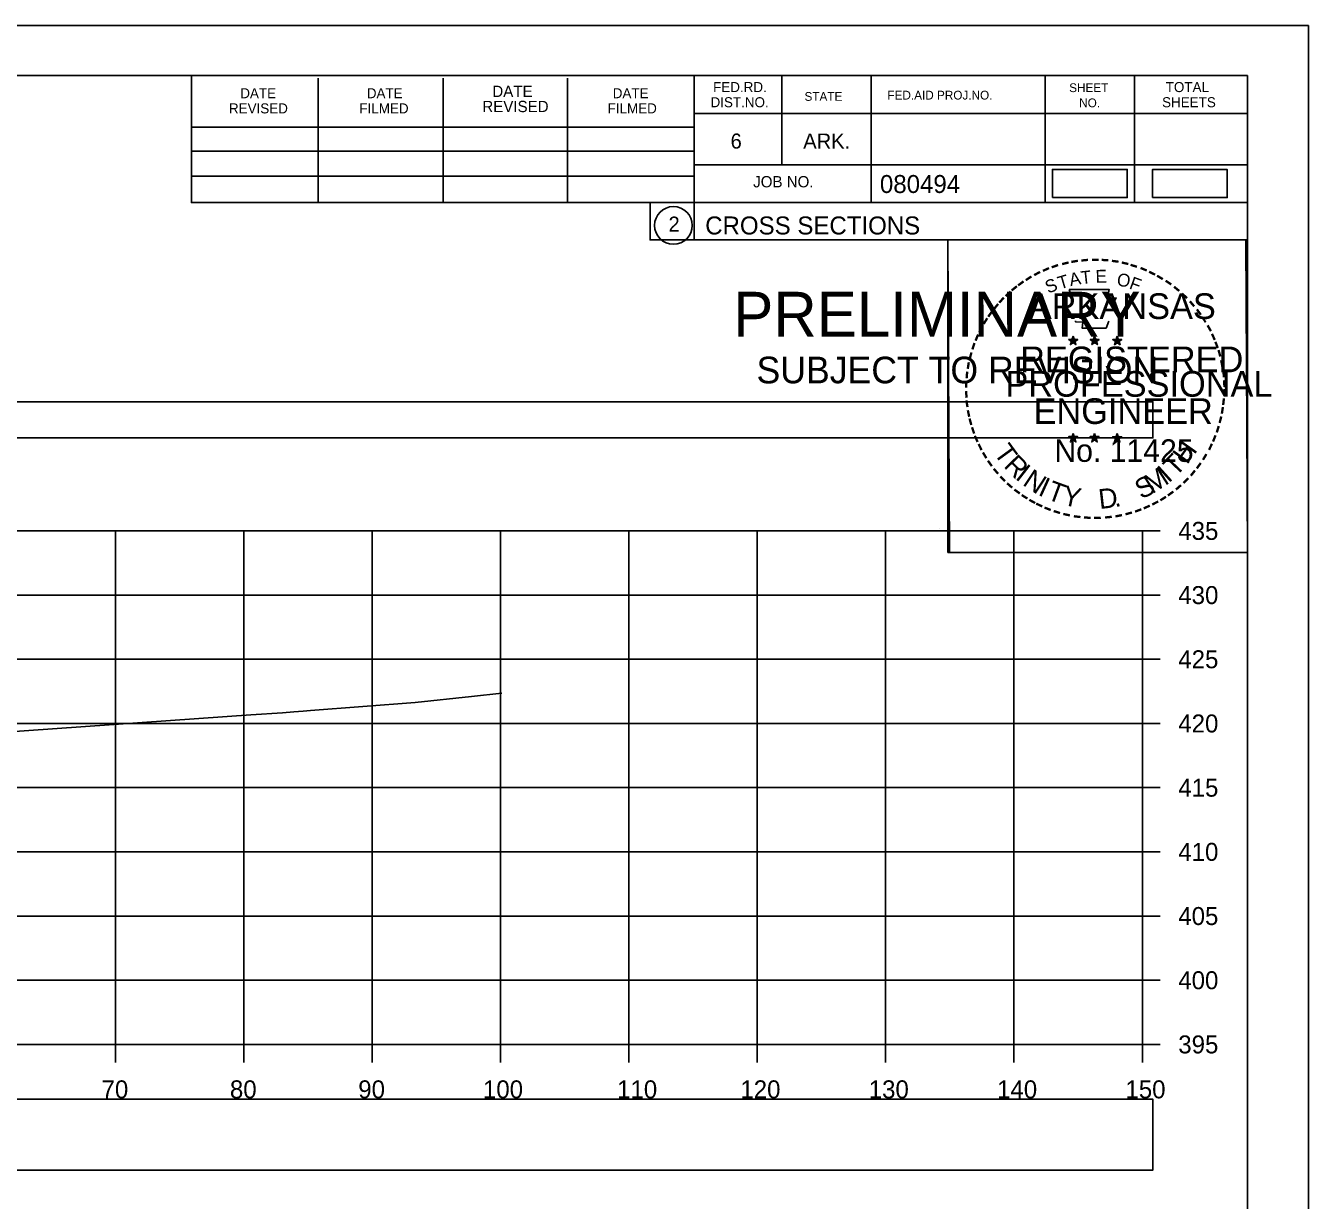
# Model space of a CAD drawing. Extents: x 1376273 to 1384221, y 378927 to 384592.
# Drawn here: x 1379454.1 to 1379554.1, y 380020.3 to 380111.8 of the extents above; entities that cross this region are included whole.
import ezdxf

# ---------------------------------------------------------------- set-up
doc = ezdxf.new("R2010")
doc.units = 0
for name, color, linetype in [('R_Axis', 7, 'Continuous'), ('R_Axis Annot', 7, 'Continuous'), ('R_Border', 7, 'Continuous'), ('R_Border PE', 7, 'Continuous'), ('R_Border Prem', 7, 'Continuous'), ('R_Drive', 7, 'Continuous'), ('R_Exist Surface', 7, 'Continuous'), ('R_Grid', 7, 'Continuous'), ('R_No Plot', 7, 'Continuous')]:
    doc.layers.add(name, color=color, linetype=linetype)

msp = doc.modelspace()

# ---------------------------------------------------------------- linework, layer by layer
at = {"layer": 'R_Axis'}
for p, q in [((1379541.147, 380032.48), (1379541.147, 380072.48)), ((1379542.547, 380072.48), (1379541.147, 380072.48)), ((1379542.547, 380067.48), (1379541.147, 380067.48)), ((1379542.547, 380062.48), (1379541.147, 380062.48)), ((1379542.547, 380057.48), (1379541.147, 380057.48)), ((1379542.547, 380052.48), (1379541.147, 380052.48)), ((1379542.547, 380047.48), (1379541.147, 380047.48)), ((1379542.547, 380042.48), (1379541.147, 380042.48)), ((1379542.547, 380037.48), (1379541.147, 380037.48)), ((1379241.147, 380032.48), (1379541.147, 380032.48)), ((1379461.147, 380031.08), (1379461.147, 380032.48)), ((1379471.147, 380031.08), (1379471.147, 380032.48)), ((1379481.147, 380031.08), (1379481.147, 380032.48)), ((1379491.147, 380031.08), (1379491.147, 380032.48)), ((1379501.147, 380031.08), (1379501.147, 380032.48)), ((1379511.147, 380031.08), (1379511.147, 380032.48)), ((1379521.147, 380031.08), (1379521.147, 380032.48)), ((1379531.147, 380031.08), (1379531.147, 380032.48)), ((1379541.147, 380031.08), (1379541.147, 380032.48)), ((1379542.547, 380032.48), (1379541.147, 380032.48))]:
    msp.add_line(p, q, dxfattribs=at)
at = {"layer": 'R_Axis Annot'}
for points in [[(1379240.169, 380079.723), (1379541.971, 380079.723), (1379541.971, 380082.54), (1379240.169, 380082.54)], [(1379240.169, 380022.687), (1379541.971, 380022.687), (1379541.971, 380028.21), (1379240.169, 380028.21)]]:
    msp.add_lwpolyline(points, close=True, dxfattribs=at)
at = {"layer": 'R_Border'}
for p, q in [((1379233.147, 380107.94), (1379549.327, 380107.94)), ((1379467.067, 380098.06), (1379467.067, 380107.94)), ((1379476.927, 380098.06), (1379476.927, 380107.74)), ((1379486.687, 380098.06), (1379486.687, 380107.74)), ((1379496.367, 380098.06), (1379496.367, 380107.74)), ((1379506.227, 380107.94), (1379506.227, 380095.14)), ((1379513.067, 380107.94), (1379513.067, 380101)), ((1379520.007, 380107.94), (1379520.007, 380098.06)), ((1379533.587, 380107.94), (1379533.587, 380098.06)), ((1379540.527, 380107.94), (1379540.527, 380098.06)), ((1379549.327, 379902.48), (1379549.327, 380107.94)), ((1379549.327, 380105), (1379506.227, 380105)), ((1379549.327, 380105.02), (1379549.327, 380105.02)), ((1379467.067, 380103.92), (1379506.227, 380103.92)), ((1379467.067, 380102.06), (1379506.227, 380102.06)), ((1379549.327, 380101), (1379506.227, 380101)), ((1379509.187, 380101), (1379549.327, 380101)), ((1379467.067, 380098.06), (1379467.067, 380100.12)), ((1379467.067, 380100.12), (1379506.227, 380100.12)), ((1379549.327, 380098.06), (1379467.067, 380098.06)), ((1379506.227, 380095.14), (1379549.327, 380095.14))]:
    msp.add_line(p, q, dxfattribs=at)
msp.add_circle((1379504.614, 380096.276), 1.467, dxfattribs=at)
at = {"layer": 'R_Border PE'}
for p, q in [((1379535.761, 380087.65), (1379535.72, 380087.398)), ((1379535.761, 380087.285), (1379535.761, 380087.65)), ((1379535.761, 380087.65), (1379535.81, 380087.4)), ((1379537.431, 380087.65), (1379537.39, 380087.398)), ((1379537.431, 380087.285), (1379537.431, 380087.65)), ((1379537.431, 380087.65), (1379537.48, 380087.4)), ((1379539.195, 380087.638), (1379539.154, 380087.386)), ((1379539.195, 380087.273), (1379539.195, 380087.638)), ((1379539.195, 380087.638), (1379539.244, 380087.388)), ((1379535.412, 380087.396), (1379535.761, 380087.285)), ((1379535.412, 380087.396), (1379535.665, 380087.351)), ((1379535.412, 380087.396), (1379535.649, 380087.274)), ((1379535.545, 380086.988), (1379535.761, 380087.285)), ((1379535.545, 380086.988), (1379535.671, 380087.232)), ((1379535.545, 380086.988), (1379535.759, 380087.205)), ((1379535.974, 380086.988), (1379535.759, 380087.202)), ((1379536.108, 380087.396), (1379535.761, 380087.285)), ((1379535.974, 380086.988), (1379535.761, 380087.285)), ((1379536.108, 380087.396), (1379535.822, 380087.347)), ((1379535.974, 380086.988), (1379535.837, 380087.279)), ((1379536.108, 380087.396), (1379535.904, 380087.294)), ((1379537.082, 380087.396), (1379537.431, 380087.285)), ((1379537.082, 380087.396), (1379537.335, 380087.351)), ((1379537.082, 380087.396), (1379537.319, 380087.274)), ((1379537.215, 380086.988), (1379537.431, 380087.285)), ((1379537.215, 380086.988), (1379537.341, 380087.232)), ((1379537.215, 380086.988), (1379537.429, 380087.205)), ((1379537.644, 380086.988), (1379537.429, 380087.202)), ((1379537.778, 380087.396), (1379537.431, 380087.285)), ((1379537.644, 380086.988), (1379537.431, 380087.285)), ((1379537.778, 380087.396), (1379537.492, 380087.347)), ((1379537.644, 380086.988), (1379537.507, 380087.279)), ((1379537.778, 380087.396), (1379537.574, 380087.294)), ((1379538.846, 380087.384), (1379539.195, 380087.273)), ((1379538.846, 380087.384), (1379539.099, 380087.339)), ((1379538.846, 380087.384), (1379539.083, 380087.262)), ((1379538.979, 380086.976), (1379539.195, 380087.273)), ((1379538.979, 380086.976), (1379539.105, 380087.22)), ((1379538.979, 380086.976), (1379539.193, 380087.193)), ((1379539.408, 380086.976), (1379539.193, 380087.19)), ((1379539.542, 380087.384), (1379539.195, 380087.273)), ((1379539.408, 380086.976), (1379539.195, 380087.273)), ((1379539.542, 380087.384), (1379539.256, 380087.335)), ((1379539.408, 380086.976), (1379539.271, 380087.267)), ((1379539.542, 380087.384), (1379539.338, 380087.282)), ((1379535.408, 380079.823), (1379535.757, 380079.712)), ((1379535.408, 380079.823), (1379535.661, 380079.778)), ((1379535.408, 380079.823), (1379535.645, 380079.701)), ((1379535.541, 380079.415), (1379535.757, 380079.712)), ((1379535.541, 380079.415), (1379535.667, 380079.659)), ((1379535.541, 380079.415), (1379535.755, 380079.632)), ((1379535.757, 380080.077), (1379535.716, 380079.825)), ((1379535.97, 380079.415), (1379535.755, 380079.629)), ((1379535.757, 380079.712), (1379535.757, 380080.077)), ((1379535.757, 380080.077), (1379535.806, 380079.827)), ((1379536.104, 380079.823), (1379535.757, 380079.712)), ((1379535.97, 380079.415), (1379535.757, 380079.712)), ((1379536.104, 380079.823), (1379535.818, 380079.774)), ((1379535.97, 380079.415), (1379535.833, 380079.706)), ((1379536.104, 380079.823), (1379535.9, 380079.721)), ((1379537.077, 380079.823), (1379537.426, 380079.712)), ((1379537.077, 380079.823), (1379537.33, 380079.778)), ((1379537.077, 380079.823), (1379537.314, 380079.701)), ((1379537.21, 380079.415), (1379537.426, 380079.712)), ((1379537.21, 380079.415), (1379537.336, 380079.659)), ((1379537.21, 380079.415), (1379537.424, 380079.632)), ((1379537.426, 380080.077), (1379537.385, 380079.825)), ((1379537.639, 380079.415), (1379537.424, 380079.629)), ((1379537.426, 380079.712), (1379537.426, 380080.077)), ((1379537.426, 380080.077), (1379537.475, 380079.827)), ((1379537.773, 380079.823), (1379537.426, 380079.712)), ((1379537.639, 380079.415), (1379537.426, 380079.712)), ((1379537.773, 380079.823), (1379537.487, 380079.774)), ((1379537.639, 380079.415), (1379537.502, 380079.706)), ((1379537.773, 380079.823), (1379537.569, 380079.721)), ((1379538.844, 380079.813), (1379539.193, 380079.702)), ((1379538.844, 380079.813), (1379539.097, 380079.768)), ((1379538.844, 380079.813), (1379539.081, 380079.691)), ((1379538.977, 380079.405), (1379539.193, 380079.702)), ((1379538.977, 380079.405), (1379539.103, 380079.649)), ((1379538.977, 380079.405), (1379539.191, 380079.622)), ((1379539.193, 380080.067), (1379539.152, 380079.815)), ((1379539.406, 380079.405), (1379539.191, 380079.619)), ((1379539.193, 380079.702), (1379539.193, 380080.067)), ((1379539.193, 380080.067), (1379539.242, 380079.817)), ((1379539.54, 380079.813), (1379539.193, 380079.702)), ((1379539.406, 380079.405), (1379539.193, 380079.702)), ((1379539.54, 380079.813), (1379539.254, 380079.764)), ((1379539.406, 380079.405), (1379539.269, 380079.696)), ((1379539.54, 380079.813), (1379539.336, 380079.711))]:
    msp.add_line(p, q, dxfattribs=at)
for points in [[(1379535.453, 380091.274), (1379535.722, 380090.447)], [(1379538.964, 380090.352), (1379539.106, 380090.636), (1379538.421, 380090.612), (1379538.569, 380091.274), (1379535.453, 380091.274)], [(1379535.945, 380088.851), (1379535.945, 380088.764), (1379536.508, 380088.745), (1379536.454, 380088.272), (1379538.324, 380088.272), (1379538.525, 380088.808)], [(1379535.761, 380087.65), (1379535.974, 380086.988), (1379535.412, 380087.396), (1379536.108, 380087.396), (1379535.545, 380086.988), (1379535.761, 380087.65)], [(1379537.431, 380087.65), (1379537.644, 380086.988), (1379537.082, 380087.396), (1379537.778, 380087.396), (1379537.215, 380086.988), (1379537.431, 380087.65)], [(1379539.195, 380087.638), (1379539.408, 380086.976), (1379538.846, 380087.384), (1379539.542, 380087.384), (1379538.979, 380086.976), (1379539.195, 380087.638)], [(1379535.757, 380080.077), (1379535.97, 380079.415), (1379535.408, 380079.823), (1379536.104, 380079.823), (1379535.541, 380079.415), (1379535.757, 380080.077)], [(1379537.426, 380080.077), (1379537.639, 380079.415), (1379537.077, 380079.823), (1379537.773, 380079.823), (1379537.21, 380079.415), (1379537.426, 380080.077)], [(1379539.193, 380080.067), (1379539.406, 380079.405), (1379538.844, 380079.813), (1379539.54, 380079.813), (1379538.977, 380079.405), (1379539.193, 380080.067)]]:
    msp.add_lwpolyline(points, dxfattribs=at)
for centre, radius in [((1379535.76, 380087.284), 0.172), ((1379535.76, 380087.284), 0.145), ((1379537.43, 380087.284), 0.172), ((1379537.43, 380087.284), 0.145), ((1379539.194, 380087.272), 0.172), ((1379539.194, 380087.272), 0.145), ((1379535.76, 380087.284), 0.116), ((1379535.76, 380087.284), 0.0991), ((1379535.76, 380087.284), 0.0747), ((1379535.76, 380087.284), 0.0495), ((1379535.76, 380087.284), 0.0296), ((1379537.43, 380087.284), 0.116), ((1379537.43, 380087.284), 0.0991), ((1379537.43, 380087.284), 0.0747), ((1379537.43, 380087.284), 0.0495), ((1379537.43, 380087.284), 0.0296), ((1379539.194, 380087.272), 0.116), ((1379539.194, 380087.272), 0.0991), ((1379539.194, 380087.272), 0.0747), ((1379539.194, 380087.272), 0.0495), ((1379539.194, 380087.272), 0.0296), ((1379535.756, 380079.711), 0.172), ((1379535.756, 380079.711), 0.145), ((1379535.756, 380079.711), 0.116), ((1379535.756, 380079.711), 0.0991), ((1379535.756, 380079.711), 0.0747), ((1379535.756, 380079.711), 0.0495), ((1379535.756, 380079.711), 0.0296), ((1379537.425, 380079.711), 0.172), ((1379537.425, 380079.711), 0.145), ((1379537.425, 380079.711), 0.116), ((1379537.425, 380079.711), 0.0991), ((1379537.425, 380079.711), 0.0747), ((1379537.425, 380079.711), 0.0495), ((1379537.425, 380079.711), 0.0296), ((1379539.192, 380079.701), 0.172), ((1379539.192, 380079.701), 0.145), ((1379539.192, 380079.701), 0.116), ((1379539.192, 380079.701), 0.0991), ((1379539.192, 380079.701), 0.0747), ((1379539.192, 380079.701), 0.0495), ((1379539.192, 380079.701), 0.0296)]:
    msp.add_circle(centre, radius, dxfattribs=at)
at = {"layer": 'R_Drive'}
for points in [[(1379534.138, 380098.448), (1379539.971, 380098.448), (1379539.971, 380100.634), (1379534.138, 380100.634)], [(1379541.935, 380098.44), (1379547.768, 380098.44), (1379547.768, 380100.626), (1379541.935, 380100.626)]]:
    msp.add_lwpolyline(points, close=True, dxfattribs=at)
at = {"layer": 'R_Exist Surface'}
msp.add_lwpolyline([(1379449.942, 380056.614), (1379471.685, 380058.144), (1379474.164, 380058.317), (1379475.054, 380058.394), (1379475.76, 380058.44), (1379476.331, 380058.49), (1379484.497, 380059.108), (1379488.875, 380059.589), (1379491.243, 380059.848)], dxfattribs=at)
at = {"layer": 'R_Grid'}
for p, q in [((1379241.147, 380072.48), (1379541.147, 380072.48)), ((1379461.147, 380032.48), (1379461.147, 380072.48)), ((1379471.147, 380032.48), (1379471.147, 380072.48)), ((1379481.147, 380032.48), (1379481.147, 380072.48)), ((1379491.147, 380032.48), (1379491.147, 380072.48)), ((1379501.147, 380032.48), (1379501.147, 380072.48)), ((1379511.147, 380032.48), (1379511.147, 380072.48)), ((1379521.147, 380032.48), (1379521.147, 380072.48)), ((1379531.147, 380032.48), (1379531.147, 380072.48)), ((1379541.147, 380032.48), (1379541.147, 380072.48)), ((1379241.147, 380067.48), (1379541.147, 380067.48)), ((1379241.147, 380062.48), (1379541.147, 380062.48)), ((1379241.147, 380057.48), (1379541.147, 380057.48)), ((1379241.147, 380052.48), (1379541.147, 380052.48)), ((1379241.147, 380047.48), (1379541.147, 380047.48)), ((1379241.147, 380042.48), (1379541.147, 380042.48)), ((1379241.147, 380037.48), (1379541.147, 380037.48)), ((1379241.147, 380032.48), (1379541.147, 380032.48))]:
    msp.add_line(p, q, dxfattribs=at)
at = {"layer": 'R_No Plot'}
for p, q in [((1379220.746, 380111.835), (1379554.08, 380111.835)), ((1379525.361, 380072.685), (1379525.361, 380072.685))]:
    msp.add_line(p, q, dxfattribs=at)
for points in [[(1379220.74, 380111.835), (1379554.08, 380111.835), (1379554.08, 379898.497), (1379220.74, 379898.497)], [(1379467.067, 380107.94), (1379467.067, 380098.06), (1379502.799, 380098.06), (1379502.799, 380095.14), (1379525.999, 380095.14), (1379525.999, 380070.808), (1379549.327, 380070.808), (1379549.327, 379902.48), (1379233.147, 379902.48), (1379233.147, 380107.94)], [(1379525.999, 380095.14), (1379549.206, 380095.14), (1379549.327, 380070.808), (1379526.119, 380070.808)]]:
    msp.add_lwpolyline(points, close=True, dxfattribs=at)

# ---------------------------------------------------------------- texts
at = {"layer": 'R_Axis Annot'}
for s, p in [('435', (1379543.947, 380071.78)), ('430', (1379543.947, 380066.78)), ('425', (1379543.947, 380061.78)), ('420', (1379543.947, 380056.78)), ('415', (1379543.947, 380051.78)), ('410', (1379543.947, 380046.78)), ('405', (1379543.947, 380041.78)), ('400', (1379543.947, 380036.78)), ('395', (1379543.947, 380031.78)), ('70', (1379460.061, 380028.28)), ('80', (1379470.061, 380028.28)), ('90', (1379480.061, 380028.28)), ('100', (1379489.775, 380028.28)), ('110', (1379500.227, 380028.28)), ('120', (1379509.83, 380028.28)), ('130', (1379519.83, 380028.28)), ('140', (1379529.83, 380028.28)), ('150', (1379539.83, 380028.28))]:
    msp.add_text(s, height=1.4, dxfattribs=at).set_placement(p)
at = {"layer": 'R_Border'}
for s, height, p in [('FED.RD.', 0.7819, (1379507.707, 380106.66)), ('TOTAL', 0.7819, (1379542.967, 380106.66)), ('DATE', 0.7819, (1379470.867, 380106.18)), ('DATE', 0.7819, (1379480.727, 380106.18)), ('DATE', 0.8792, (1379490.507, 380106.28)), ('DATE', 0.7819, (1379499.887, 380106.18)), ('STATE', 0.684, (1379514.827, 380105.98)), ('FED.AID PROJ.NO.', 0.684, (1379521.287, 380106.08)), ('SHEET', 0.684, (1379535.447, 380106.66)), ('REVISED', 0.7819, (1379469.987, 380105)), ('FILMED', 0.7819, (1379480.147, 380105)), ('REVISED', 0.8792, (1379489.727, 380105.1)), ('FILMED', 0.7819, (1379499.487, 380105)), ('DIST.NO.', 0.7819, (1379507.507, 380105.48)), ('NO.', 0.684, (1379536.227, 380105.48)), ('SHEETS', 0.7819, (1379542.687, 380105.48)), ('6', 1.172, (1379509.067, 380102.26)), ('ARK.', 1.1723, (1379514.727, 380102.26)), ('JOB NO.', 0.8792, (1379510.827, 380099.24)), ('080494', 1.4, (1379520.703, 380098.8)), ('2', 1.172, (1379504.231, 380095.79)), ('CROSS SECTIONS', 1.4, (1379507.091, 380095.57))]:
    msp.add_text(s, height=height, rotation=360, dxfattribs=at).set_placement(p)
at = {"layer": 'R_Border PE'}
for s, height, rotation, p in [('-', 1.6, 13.63015, (1379534.951, 380092.642)), ('-', 1.6, 10.21935, (1379535.629, 380092.804)), ('-', 1.6, 5.89682, (1379536.358, 380092.914)), ('-', 1.6, 0.18623, (1379537.13, 380092.986)), ('-', 1.6, 357.74304, (1379537.853, 380092.973)), ('-', 1.6, 352.16172, (1379538.597, 380092.917)), ('-', 1.6, 347.20489, (1379539.316, 380092.803)), ('-', 1.6, 28.79182, (1379532.934, 380091.815)), ('-', 1.6, 24.30721, (1379533.567, 380092.132)), ('-', 1.6, 19.17608, (1379534.201, 380092.401)), ('T', 1, 16.4036, (1379534.722, 380091.283)), ('A', 1, 11.21318, (1379535.548, 380091.534)), ('T', 1, 6.02276, (1379536.397, 380091.7)), ('E', 1, 0.83234, (1379537.502, 380091.81)), ('O', 1, 350.4515, (1379539.106, 380091.6)), ('-', 1.6, 342.3362, (1379539.951, 380092.648)), ('-', 1.6, 337.85509, (1379540.686, 380092.425)), ('-', 1.6, 334.12109, (1379541.317, 380092.154)), ('-', 1.6, 329.64089, (1379541.896, 380091.871)), ('-', 1.6, 38.95066, (1379531.283, 380090.672)), ('-', 1.6, 36.23174, (1379531.759, 380091.05)), ('-', 1.6, 34.06357, (1379532.337, 380091.445)), ('S', 1, 21.59401, (1379533.808, 380090.952)), ('F', 1, 340.07066, (1379540.06, 380091.372)), ('-', 1.6, 325.86266, (1379542.539, 380091.51)), ('-', 1.6, 320.52971, (1379543.149, 380091.084)), ('-', 1.6, 48.42305, (1379530.402, 380089.777)), ('-', 1.6, 42.96224, (1379530.85, 380090.255)), ('ARKANSAS', 2, 360, (1379532.306, 380088.986)), ('-', 1.6, 315.57859, (1379543.748, 380090.596)), ('-', 1.6, 309.87973, (1379544.317, 380090.046)), ('-', 1.6, 54.23247, (1379529.586, 380088.724)), ('-', 1.6, 50.61417, (1379529.999, 380089.291)), ('-', 1.6, 306.65218, (1379544.842, 380089.444)), ('-', 1.6, 62.87135, (1379528.948, 380087.583)), ('-', 1.6, 58.07063, (1379529.261, 380088.197)), ('-', 1.4, 303.67529, (1379545.328, 380088.876)), ('-', 1.6, 299.66835, (1379545.647, 380088.269)), ('-', 1.6, 67.77427, (1379528.689, 380086.972)), ('-', 1.6, 294.66279, (1379545.971, 380087.657)), ('-', 1.6, 72.39447, (1379528.47, 380086.342)), ('REGISTERED', 2, 360, (1379531.628, 380084.837)), ('DWB', 0.01, 360, (1379535.748, 380087.279)), ('DWB', 0.01, 360, (1379537.418, 380087.279)), ('DWB', 0.01, 360, (1379539.182, 380087.268)), ('-', 1.6, 290.57283, (1379546.228, 380087.08)), ('-', 1.6, 285.12326, (1379546.462, 380086.5)), ('-', 1.6, 81.20126, (1379528.141, 380084.915)), ('-', 1.6, 75.46096, (1379528.273, 380085.628)), ('-', 1.6, 280.54934, (1379546.662, 380085.758)), ('-', 1.6, 85.18634, (1379528.065, 380084.224)), ('PROFESSIONAL', 2, 360, (1379530.48, 380082.933)), ('-', 1.6, 276.59616, (1379546.824, 380084.99)), ('-', 1.6, 89.06224, (1379528.04, 380083.523)), ('-', 1.6, 274.33011, (1379546.884, 380084.268)), ('-', 1.6, 269.94067, (1379546.918, 380083.636)), ('-', 1.6, 94.19588, (1379528.075, 380082.798)), ('-', 1.6, 98.94793, (1379528.147, 380082.131)), ('ENGINEER', 2, 360, (1379532.667, 380080.808)), ('-', 1.6, 263.5172, (1379546.899, 380082.97)), ('-', 1.6, 101.71495, (1379528.282, 380081.398)), ('-', 1.6, 260.99529, (1379546.828, 380082.316)), ('-', 1.6, 105.45785, (1379528.444, 380080.803)), ('-', 1.6, 109.08742, (1379528.659, 380080.172)), ('-', 1.6, 252.86809, (1379546.537, 380080.918)), ('-', 1.6, 255.7626, (1379546.718, 380081.638)), ('-', 1.6, 114.06432, (1379528.913, 380079.576)), ('No. 11425', 1.757, 360, (1379534.294, 380077.857)), ('DWB', 0.01, 360, (1379535.744, 380079.706)), ('DWB', 0.01, 360, (1379537.413, 380079.707)), ('DWB', 0.01, 360, (1379539.18, 380079.697)), ('H', 1.54, 54.60883, (1379544.637, 380077.585)), ('-', 1.6, 247.88866, (1379546.314, 380080.245)), ('-', 1.6, 115.72885, (1379529.218, 380078.958)), ('-', 1.6, 120.44712, (1379529.575, 380078.372)), ('T', 1.54, 306.04056, (1379529.517, 380078.55)), ('R', 1.54, 314.00497, (1379530.279, 380077.502)), ('T', 1.54, 46.64442, (1379543.747, 380076.642)), ('-', 1.6, 239.07125, (1379545.658, 380078.864)), ('-', 1.6, 244.61971, (1379546.052, 380079.616)), ('-', 1.6, 125.89344, (1379529.978, 380077.811)), ('I', 1.54, 321.96938, (1379531.18, 380076.57)), ('M', 1.54, 32.65632, (1379541.901, 380075.317)), ('I', 1.54, 42.11359, (1379543.186, 380076.164)), ('-', 1.6, 233.84524, (1379545.256, 380078.211)), ('-', 1.6, 130.71812, (1379530.44, 380077.259)), ('-', 1.6, 134.22381, (1379530.957, 380076.714)), ('N', 1.54, 326.50021, (1379531.747, 380076.098)), ('I', 1.54, 335.36034, (1379532.955, 380075.312)), ('S', 1.54, 26.9312, (1379541.063, 380074.911)), ('-', 1.6, 225.76533, (1379544.347, 380077.081)), ('-', 1.6, 231.25377, (1379544.826, 380077.645)), ('-', 1.6, 138.93382, (1379531.482, 380076.25)), ('-', 1.6, 144.64634, (1379532.038, 380075.844)), ('T', 1.54, 339.89117, (1379533.616, 380074.985)), ('Y', 1.54, 347.85558, (1379534.833, 380074.539)), ('D', 1.54, 6.39691, (1379537.818, 380074.181)), ('-', 1.6, 215.73633, (1379543.276, 380076.1)), ('-', 1.6, 221.08509, (1379543.825, 380076.572)), ('-', 1.6, 148.08978, (1379532.599, 380075.473)), ('-', 1.6, 151.57039, (1379533.178, 380075.148)), ('-', 1.6, 154.60019, (1379533.7, 380074.901)), ('.', 1.54, 13.76417, (1379539.01, 380074.308)), ('-', 1.6, 204.25161, (1379541.56, 380075.048)), ('-', 1.6, 207.35684, (1379542.184, 380075.367)), ('-', 1.6, 212.24909, (1379542.742, 380075.713)), ('-', 1.6, 158.56121, (1379534.324, 380074.647)), ('-', 1.6, 162.79826, (1379535.011, 380074.434)), ('-', 1.6, 167.55551, (1379535.726, 380074.27)), ('-', 1.6, 173.11546, (1379536.498, 380074.16)), ('-', 1.6, 176.51827, (1379537.246, 380074.107)), ('-', 1.6, 181.59176, (1379537.99, 380074.126)), ('-', 1.6, 185.81666, (1379538.799, 380074.202)), ('-', 1.6, 191.28576, (1379539.535, 380074.334)), ('-', 1.6, 195.47429, (1379540.264, 380074.533)), ('-', 1.6, 200.71842, (1379540.941, 380074.775))]:
    msp.add_text(s, height=height, rotation=rotation, dxfattribs=at).set_placement(p)
at = {"layer": 'R_Border Prem'}
for s, height, p in [('PRELIMINARY', 3.5, (1379509.278, 380087.604)), ('DWB', 0.01, (1379510.025, 380089.453)), ('SUBJECT TO REVISION', 2.07511, (1379511.087, 380083.975))]:
    msp.add_text(s, height=height, rotation=360, dxfattribs=at).set_placement(p)

doc.saveas('drawing.dxf')
